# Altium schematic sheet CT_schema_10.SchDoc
size 274 x 160 mm
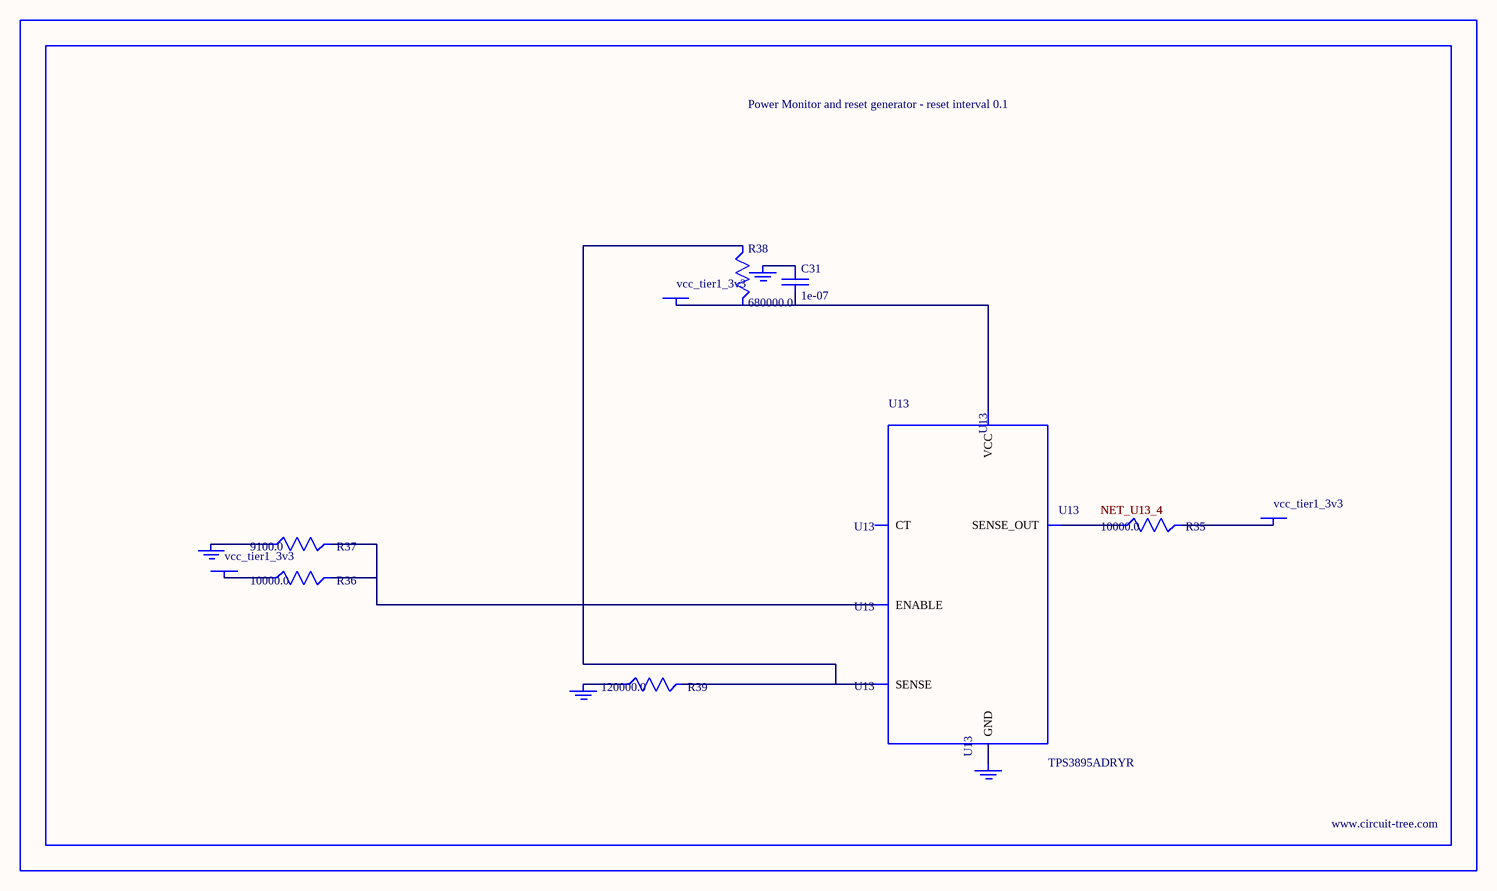
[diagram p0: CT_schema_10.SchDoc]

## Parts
BORDER9  (no value)
C31  1e-07  [C0402]
GND_INSTANCE_9_0  (no value)
GND_INSTANCE_9_1  (no value)
GND_INSTANCE_9_2  (no value)
GND_INSTANCE_9_3  (no value)
POWER_INSTANCE_9_0  vcc_tier1_3v3
POWER_INSTANCE_9_1  vcc_tier1_3v3
POWER_INSTANCE_9_2  vcc_tier1_3v3
R35  10000.0  [R0603]
R36  10000.0  [R0603]
R37  9100.0  [R0603]
R38  680000.0  [R0603]
R39  120000.0  [R0603]
U13  TPS3895ADRYR  [SON-6]

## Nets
NetC31_1: C31.1 GND_INSTANCE_9_2.0(GND)
NetC31_2: C31.2 POWER_INSTANCE_9_2.0(PWR) R38.2 U13.6(VCC)
NetGND_INSTANCE_9_0_0: GND_INSTANCE_9_0.0(GND) R37.1
NetGND_INSTANCE_9_1_0: GND_INSTANCE_9_1.0(GND) R39.1
NetGND_INSTANCE_9_3_0: GND_INSTANCE_9_3.0(GND) U13.2(GND)
NetPOWER_INSTANCE_9_0_0: POWER_INSTANCE_9_0.0(PWR) R36.1
NetPOWER_INSTANCE_9_1_0: POWER_INSTANCE_9_1.0(PWR) R35.2
NetR35_1: R35.1 U13.4(SENSE_OUT)
NetR36_2: R36.2 R37.2 U13.1(ENABLE)
NetR38_1: R38.1 R39.2 U13.3(SENSE)

Not connected (* = marked no-connect by the designer): U13 5(CT)

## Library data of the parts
BORDER9 = BORDER_PAGE9
C31 = C0402C104K3RACTU
GND_INSTANCE_9_0-GND_INSTANCE_9_3 = GND
POWER_INSTANCE_9_0-POWER_INSTANCE_9_2 = PWR
R35 R36 = RC0603JR-0710KL
R37 = RC0603JR-079K1L
R38 = RC0603JR-07680KL
R39 = RC0603JR-07120KL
